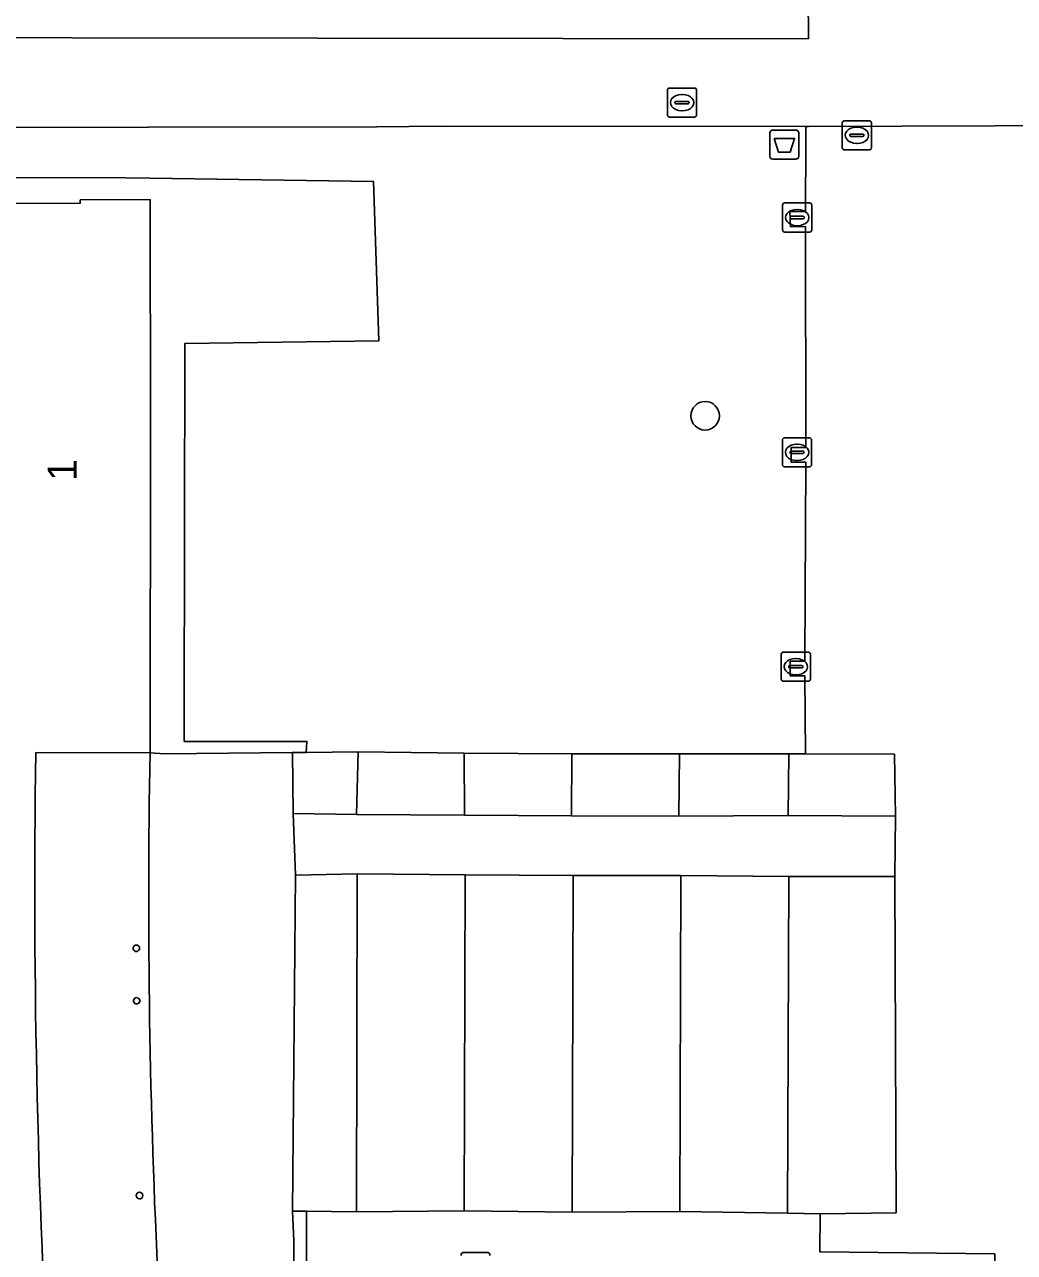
# Model space of a CAD drawing. Extents: x 161477 to 163040, y 383680 to 384871.
# Drawn here: x 162161.99 to 162195.95, y 384149.25 to 384191.39 of the extents above; entities that cross this region are included whole.
import ezdxf

# ---------------------------------------------------------------- set-up
doc = ezdxf.new("R2010")
doc.units = 0
for name, color, linetype in [('IMGEO_Afvalbak', 7, 'Continuous'), ('IMGEO_Boom', 7, 'Continuous'), ('IMGEO_Brandkraan', 7, 'Continuous'), ('IMGEO_Groenvoorziening', 7, 'Continuous'), ('IMGEO_Kolk', 7, 'Continuous'), ('IMGEO_Lichtmast', 7, 'Continuous'), ('IMGEO_Muur', 7, 'Continuous'), ('IMGEO_Pand', 7, 'Continuous'), ('IMGEO_Pand_nummerreeks', 7, 'Continuous'), ('IMGEO_Rioolput', 7, 'Continuous'), ('IMGEO_Voetpad_op_trap', 7, 'Continuous'), ('IMGEO_Voetpad_open', 7, 'Continuous')]:
    doc.layers.add(name, color=color, linetype=linetype)

msp = doc.modelspace()

# ---------------------------------------------------------------- linework, layer by layer
at = {"layer": 'IMGEO_Afvalbak'}
for p, q in [((162187.558, 384186.867), (162187.558, 384187.667)), ((162187.558, 384187.667), (162187.558, 384186.867)), ((162187.658, 384187.767), (162188.448, 384187.767)), ((162188.448, 384187.767), (162187.658, 384187.767)), ((162188.548, 384187.667), (162188.548, 384186.867)), ((162188.548, 384186.867), (162188.548, 384187.667)), ((162188.448, 384186.767), (162187.658, 384186.767)), ((162187.658, 384186.767), (162188.448, 384186.767))]:
    msp.add_line(p, q, dxfattribs=at)
msp.add_lwpolyline([(162187.701, 384187.481), (162188.405, 384187.481), (162188.256, 384187.011), (162187.85, 384187.011), (162187.701, 384187.481)], dxfattribs=at)
for centre, start, end in [((162187.658, 384187.667), 90, 180), ((162187.658, 384187.667), 90, 180), ((162188.448, 384187.667), 0, 90), ((162188.448, 384187.667), 360, 90), ((162187.658, 384186.867), 180, 270), ((162187.658, 384186.867), 180, 270), ((162188.448, 384186.867), 270, 0), ((162188.448, 384186.867), 270, 0)]:
    msp.add_arc(centre, 0.1, start, end, dxfattribs=at)
at = {"layer": 'IMGEO_Boom'}
msp.add_circle((162185.339, 384177.962), 0.489, dxfattribs=at)
at = {"layer": 'IMGEO_Brandkraan'}
for p, q in [((162190.044, 384187.161), (162190.044, 384188.013)), ((162190.119, 384188.087), (162190.971, 384188.087)), ((162191.045, 384188.013), (162191.045, 384187.161)), ((162190.303, 384187.581), (162190.303, 384187.593)), ((162190.741, 384187.544), (162190.343, 384187.544)), ((162190.346, 384187.63), (162190.744, 384187.63)), ((162190.532, 384187.867), (162190.557, 384187.867)), ((162190.787, 384187.593), (162190.787, 384187.581)), ((162190.555, 384187.307), (162190.53, 384187.307)), ((162190.971, 384187.087), (162190.119, 384187.087))]:
    msp.add_line(p, q, dxfattribs=at)
for points in [[(162190.044, 384187.161), (162190.044, 384188.013)], [(162190.119, 384188.087), (162190.971, 384188.087)], [(162191.045, 384188.013), (162191.045, 384187.161)], [(162190.971, 384187.087), (162190.119, 384187.087)]]:
    msp.add_lwpolyline(points, dxfattribs=at)
for centre, radius, start, end in [((162190.121, 384188.011), 0.0765, 91.552, 178.448), ((162190.121, 384188.011), 0.0765, 91.552, 178.448), ((162190.969, 384188.011), 0.0765, 1.552, 88.448), ((162190.969, 384188.011), 0.0765, 1.552, 88.448), ((162190.343, 384187.59), 0.0403, 85.8775, 175.7526), ((162190.34, 384187.58), 0.0366, 178.938, 274.7102), ((162190.744, 384187.587), 0.043, 264.8664, 352.4533), ((162190.748, 384187.592), 0.0386, 1.7309, 96.639), ((162190.121, 384187.163), 0.0765, 181.552, 268.448), ((162190.121, 384187.163), 0.0765, 181.552, 268.448), ((162190.969, 384187.163), 0.0765, 271.552, 358.448), ((162190.969, 384187.163), 0.0765, 271.552, 358.448)]:
    msp.add_arc(centre, radius, start, end, dxfattribs=at)
for centre, major_axis, ratio, start_param, end_param in [((162190.531, 384187.587), (-0.387, 0.002), 0.722429, 4.712389, 7.853982), ((162190.556, 384187.587), (-0.39, 0.002), 0.717154, 1.570796, 4.712389)]:
    msp.add_ellipse(centre, major_axis=major_axis, ratio=ratio, start_param=start_param, end_param=end_param, dxfattribs=at)
at = {"layer": 'IMGEO_Groenvoorziening'}
for points in [[(162104.681, 384192.792), (162104.654, 384191.016), (162188.881, 384190.9), (162188.873, 384192.38)], [(162155.137, 384186.146), (162165.447, 384186.122), (162166.287, 384186.12), (162173.964, 384185.999), (162174.149, 384180.537), (162167.49, 384180.44), (162167.473, 384167.492), (162167.472, 384166.788), (162171.68, 384166.786), (162171.652, 384166.414), (162173.434, 384166.426), (162177.077, 384166.387), (162180.765, 384166.363), (162184.462, 384166.363), (162188.21, 384166.358), (162188.781, 384166.357), (162188.757, 384169.041), (162188.257, 384169.043), (162188.259, 384169.543), (162188.759, 384169.541), (162188.787, 384176.376), (162188.287, 384176.375), (162188.287, 384176.875), (162188.787, 384176.876), (162188.78, 384184.461), (162188.267, 384184.45), (162188.245, 384184.974), (162188.776, 384184.968), (162188.79, 384187.341), (162188.794, 384187.886), (162176.282, 384187.902), (162174.081, 384187.881), (162166.246, 384187.869), (162148.931, 384187.832)]]:
    msp.add_lwpolyline(points, dxfattribs=at)
for points in [[(162173.964, 384185.999), (162166.287, 384186.12), (162165.447, 384186.122), (162155.137, 384186.146), (162149.501, 384186.002), (162149.508, 384185.702), (162149.52, 384185.242), (162163.904, 384185.258), (162163.904, 384185.368), (162166.305, 384185.379), (162166.305, 384185.279), (162166.316, 384177.667), (162166.297, 384166.401), (162166.795, 384166.359), (162171.183, 384166.409), (162171.652, 384166.414), (162171.68, 384166.786), (162167.472, 384166.788), (162167.473, 384167.492), (162167.49, 384180.44), (162174.149, 384180.537)], [(162195.277, 384149.207), (162189.268, 384149.278), (162189.285, 384150.584), (162188.164, 384150.602), (162184.472, 384150.653), (162180.775, 384150.64), (162177.072, 384150.682), (162173.379, 384150.65), (162171.665, 384150.667), (162171.665, 384149.89), (162171.667, 384147.235), (162172.666, 384147.297), (162173.098, 384141.826), (162173.243, 384140.073), (162195.003, 384142.981), (162195.257, 384143.015), (162195.259, 384143.722)]]:
    msp.add_lwpolyline(points, close=True, dxfattribs=at)
at = {"layer": 'IMGEO_Kolk'}
for p, q in [((162187.996, 384184.338), (162187.996, 384185.19)), ((162188.071, 384185.264), (162188.923, 384185.264)), ((162188.484, 384185.044), (162188.509, 384185.044)), ((162188.997, 384185.19), (162188.997, 384184.338)), ((162188.255, 384184.758), (162188.255, 384184.77)), ((162188.693, 384184.721), (162188.295, 384184.721)), ((162188.298, 384184.807), (162188.696, 384184.807)), ((162188.739, 384184.77), (162188.739, 384184.758)), ((162188.923, 384184.264), (162188.071, 384184.264)), ((162188.507, 384184.484), (162188.482, 384184.484)), ((162187.99, 384176.282), (162187.99, 384177.134)), ((162188.065, 384177.208), (162188.917, 384177.208)), ((162188.478, 384176.988), (162188.503, 384176.988)), ((162188.991, 384177.134), (162188.991, 384176.282)), ((162188.249, 384176.702), (162188.249, 384176.714)), ((162188.687, 384176.665), (162188.289, 384176.665)), ((162188.292, 384176.751), (162188.69, 384176.751)), ((162188.733, 384176.714), (162188.733, 384176.702)), ((162188.917, 384176.208), (162188.065, 384176.208)), ((162188.501, 384176.428), (162188.476, 384176.428)), ((162188.026, 384169.852), (162188.878, 384169.852)), ((162187.951, 384168.926), (162187.951, 384169.778)), ((162188.439, 384169.632), (162188.464, 384169.632)), ((162188.952, 384169.778), (162188.952, 384168.926)), ((162188.21, 384169.346), (162188.21, 384169.358)), ((162188.648, 384169.309), (162188.25, 384169.309)), ((162188.253, 384169.395), (162188.651, 384169.395)), ((162188.462, 384169.072), (162188.437, 384169.072)), ((162188.694, 384169.358), (162188.694, 384169.346)), ((162188.878, 384168.852), (162188.026, 384168.852))]:
    msp.add_line(p, q, dxfattribs=at)
for points in [[(162187.996, 384184.338), (162187.996, 384185.19)], [(162188.071, 384185.264), (162188.923, 384185.264)], [(162188.997, 384185.19), (162188.997, 384184.338)], [(162188.923, 384184.264), (162188.071, 384184.264)], [(162187.99, 384176.282), (162187.99, 384177.134)], [(162188.065, 384177.208), (162188.917, 384177.208)], [(162188.991, 384177.134), (162188.991, 384176.282)], [(162188.917, 384176.208), (162188.065, 384176.208)], [(162188.026, 384169.852), (162188.878, 384169.852)], [(162187.951, 384168.926), (162187.951, 384169.778)], [(162188.952, 384169.778), (162188.952, 384168.926)], [(162188.878, 384168.852), (162188.026, 384168.852)]]:
    msp.add_lwpolyline(points, dxfattribs=at)
for centre, radius, start, end in [((162188.073, 384185.188), 0.0765, 91.552, 178.448), ((162188.073, 384185.188), 0.0765, 91.552, 178.448), ((162188.921, 384185.188), 0.0765, 1.552, 88.448), ((162188.921, 384185.188), 0.0765, 1.552, 88.448), ((162188.295, 384184.767), 0.0403, 85.8775, 175.7526), ((162188.292, 384184.757), 0.0366, 178.938, 274.7102), ((162188.696, 384184.764), 0.043, 264.8664, 352.4533), ((162188.7, 384184.769), 0.0386, 1.7309, 96.639), ((162188.073, 384184.34), 0.0765, 181.552, 268.448), ((162188.073, 384184.34), 0.0765, 181.552, 268.448), ((162188.921, 384184.34), 0.0765, 271.552, 358.448), ((162188.921, 384184.34), 0.0765, 271.552, 358.448), ((162188.067, 384177.132), 0.0765, 91.552, 178.448), ((162188.067, 384177.132), 0.0765, 91.552, 178.448), ((162188.915, 384177.132), 0.0765, 1.552, 88.448), ((162188.915, 384177.132), 0.0765, 1.552, 88.448), ((162188.289, 384176.711), 0.0403, 85.8775, 175.7526), ((162188.286, 384176.701), 0.0366, 178.938, 274.7102), ((162188.69, 384176.708), 0.043, 264.8664, 352.4533), ((162188.694, 384176.713), 0.0386, 1.7309, 96.639), ((162188.067, 384176.284), 0.0765, 181.552, 268.448), ((162188.067, 384176.284), 0.0765, 181.552, 268.448), ((162188.915, 384176.284), 0.0765, 271.552, 358.448), ((162188.915, 384176.284), 0.0765, 271.552, 358.448), ((162188.028, 384169.776), 0.0765, 91.552, 178.448), ((162188.028, 384169.776), 0.0765, 91.552, 178.448), ((162188.876, 384169.776), 0.0765, 1.552, 88.448), ((162188.876, 384169.776), 0.0765, 1.552, 88.448), ((162188.25, 384169.355), 0.0403, 85.8775, 175.7526), ((162188.247, 384169.345), 0.0366, 178.938, 274.7102), ((162188.651, 384169.352), 0.043, 264.8664, 352.4533), ((162188.655, 384169.357), 0.0386, 1.7309, 96.639), ((162188.028, 384168.928), 0.0765, 181.552, 268.448), ((162188.028, 384168.928), 0.0765, 181.552, 268.448), ((162188.876, 384168.928), 0.0765, 271.552, 358.448), ((162188.876, 384168.928), 0.0765, 271.552, 358.448)]:
    msp.add_arc(centre, radius, start, end, dxfattribs=at)
for centre, major_axis, ratio, start_param, end_param in [((162188.483, 384184.764), (-0.387, 0.002), 0.722429, 4.712389, 7.853982), ((162188.508, 384184.764), (-0.39, 0.002), 0.717154, 1.570796, 4.712389), ((162188.477, 384176.708), (-0.387, 0.002), 0.722429, 4.712389, 7.853982), ((162188.502, 384176.708), (-0.39, 0.002), 0.717154, 1.570796, 4.712389), ((162188.438, 384169.352), (-0.387, 0.002), 0.722429, 4.712389, 7.853982), ((162188.463, 384169.352), (-0.39, 0.002), 0.717154, 1.570796, 4.712389)]:
    msp.add_ellipse(centre, major_axis=major_axis, ratio=ratio, start_param=start_param, end_param=end_param, dxfattribs=at)
at = {"layer": 'IMGEO_Lichtmast'}
for p, q in [((162177.067, 384149.254), (162177.857, 384149.254)), ((162177.857, 384149.254), (162177.067, 384149.254))]:
    msp.add_line(p, q, dxfattribs=at)
for centre, start, end in [((162177.067, 384149.154), 90, 180), ((162177.067, 384149.154), 90, 180), ((162177.857, 384149.154), 0, 90), ((162177.857, 384149.154), 360, 90)]:
    msp.add_arc(centre, 0.1, start, end, dxfattribs=at)
at = {"layer": 'IMGEO_Muur'}
msp.add_lwpolyline([(162171.667, 384147.235), (162171.665, 384149.89), (162171.665, 384150.667), (162171.189, 384150.672), (162171.234, 384149.651), (162171.223, 384147.253)], dxfattribs=at)
at = {"layer": 'IMGEO_Pand'}
msp.add_lwpolyline([(162162.377, 384166.407), (162166.297, 384166.401), (162166.316, 384177.667), (162166.305, 384185.279), (162166.305, 384185.379), (162163.904, 384185.368), (162163.904, 384185.258), (162149.52, 384185.242), (162147.865, 384185.24), (162061.36, 384185.144)], dxfattribs=at)
for centre, radius, start, end in [((162474.563, 384161.839), 312.22, 179.16169, 183.5032), ((162165.827, 384159.691), 0.111, 33.528, 253.2831), ((162165.828, 384159.69), 0.11, 252.7297, 34.0814), ((162165.838, 384157.889), 0.109, 33.548, 302.6747), ((162165.839, 384157.889), 0.108, 302.3757, 33.847), ((162165.939, 384151.206), 0.113, 49.5701, 310.4299), ((162165.94, 384151.206), 0.112, 310.1122, 49.8878)]:
    msp.add_arc(centre, radius, start, end, dxfattribs=at)
at = {"layer": 'IMGEO_Rioolput'}
for p, q in [((162184.12, 384189.209), (162184.972, 384189.209)), ((162184.045, 384188.283), (162184.045, 384189.135)), ((162184.533, 384188.989), (162184.558, 384188.989)), ((162185.046, 384189.135), (162185.046, 384188.283)), ((162184.304, 384188.703), (162184.304, 384188.715)), ((162184.742, 384188.666), (162184.344, 384188.666)), ((162184.347, 384188.752), (162184.745, 384188.752)), ((162184.556, 384188.429), (162184.531, 384188.429)), ((162184.788, 384188.715), (162184.788, 384188.703)), ((162184.972, 384188.209), (162184.12, 384188.209))]:
    msp.add_line(p, q, dxfattribs=at)
for points in [[(162184.12, 384189.209), (162184.972, 384189.209)], [(162184.045, 384188.283), (162184.045, 384189.135)], [(162185.046, 384189.135), (162185.046, 384188.283)], [(162184.972, 384188.209), (162184.12, 384188.209)]]:
    msp.add_lwpolyline(points, dxfattribs=at)
for centre, radius, start, end in [((162184.122, 384189.133), 0.0765, 91.552, 178.448), ((162184.122, 384189.133), 0.0765, 91.552, 178.448), ((162184.97, 384189.133), 0.0765, 1.552, 88.448), ((162184.97, 384189.133), 0.0765, 1.552, 88.448), ((162184.344, 384188.712), 0.0403, 85.8775, 175.7526), ((162184.341, 384188.702), 0.0366, 178.938, 274.7102), ((162184.745, 384188.709), 0.043, 264.8664, 352.4533), ((162184.749, 384188.714), 0.0386, 1.7309, 96.639), ((162184.122, 384188.285), 0.0765, 181.552, 268.448), ((162184.122, 384188.285), 0.0765, 181.552, 268.448), ((162184.97, 384188.285), 0.0765, 271.552, 358.448), ((162184.97, 384188.285), 0.0765, 271.552, 358.448)]:
    msp.add_arc(centre, radius, start, end, dxfattribs=at)
for centre, major_axis, ratio, start_param, end_param in [((162184.532, 384188.709), (-0.387, 0.002), 0.722429, 4.712389, 7.853982), ((162184.557, 384188.709), (-0.39, 0.002), 0.717154, 1.570796, 4.712389)]:
    msp.add_ellipse(centre, major_axis=major_axis, ratio=ratio, start_param=start_param, end_param=end_param, dxfattribs=at)
at = {"layer": 'IMGEO_Voetpad_op_trap'}
for points in [[(162173.434, 384166.426), (162171.652, 384166.414), (162171.183, 384166.409), (162171.207, 384164.316), (162173.382, 384164.281)], [(162177.077, 384166.387), (162173.434, 384166.426), (162173.382, 384164.281), (162177.087, 384164.255)], [(162180.765, 384166.363), (162177.077, 384166.387), (162177.087, 384164.255), (162180.757, 384164.236)], [(162184.462, 384166.363), (162180.765, 384166.363), (162180.757, 384164.236), (162184.438, 384164.225)], [(162188.21, 384166.358), (162184.462, 384166.363), (162184.438, 384164.225), (162188.189, 384164.251)], [(162191.837, 384166.35), (162188.781, 384166.357), (162188.21, 384166.358), (162188.189, 384164.251), (162191.873, 384164.221)], [(162173.407, 384162.25), (162171.289, 384162.195), (162171.189, 384150.672), (162171.665, 384150.667), (162173.379, 384150.65)], [(162177.112, 384162.209), (162173.407, 384162.25), (162173.379, 384150.65), (162177.072, 384150.682)], [(162180.81, 384162.192), (162177.112, 384162.209), (162177.072, 384150.682), (162180.775, 384150.64)], [(162184.506, 384162.192), (162180.81, 384162.192), (162180.775, 384150.64), (162184.472, 384150.653)], [(162188.205, 384162.158), (162184.506, 384162.192), (162184.472, 384150.653), (162188.164, 384150.602)], [(162191.85, 384162.152), (162188.205, 384162.158), (162188.164, 384150.602), (162189.285, 384150.584), (162191.888, 384150.614)]]:
    msp.add_lwpolyline(points, close=True, dxfattribs=at)
at = {"layer": 'IMGEO_Voetpad_open'}
for points in [[(162188.873, 384192.38), (162188.881, 384190.9), (162104.654, 384191.016), (162102.274, 384191.019), (162083.053, 384190.907), (162080.169, 384190.88), (162056.233, 384190.888), (162041.924, 384190.961), (162036.69, 384190.945), (162021.037, 384190.964), (161965.965, 384191.055), (161965.985, 384199.331)], [(162111.682, 384187.774), (162130.783, 384187.804), (162148.931, 384187.832), (162166.246, 384187.869), (162174.081, 384187.881), (162176.282, 384187.902), (162188.794, 384187.886), (162188.88, 384187.886), (162198.463, 384187.921), (162202.167, 384187.934), (162219.54, 384187.974), (162232.681, 384187.987)], [(162198.463, 384187.921), (162188.88, 384187.886), (162188.794, 384187.886), (162188.79, 384187.341), (162188.776, 384184.968), (162188.245, 384184.974), (162188.267, 384184.45), (162188.78, 384184.461), (162188.787, 384176.876), (162188.287, 384176.875), (162188.287, 384176.375), (162188.787, 384176.376), (162188.759, 384169.541), (162188.259, 384169.543), (162188.257, 384169.043), (162188.757, 384169.041), (162188.781, 384166.357), (162191.837, 384166.35), (162191.873, 384164.221), (162191.85, 384162.152), (162191.888, 384150.614), (162189.285, 384150.584), (162189.268, 384149.278), (162195.277, 384149.207)], [(162166.297, 384166.401), (162162.377, 384166.407)], [(162171.289, 384162.195), (162171.207, 384164.316), (162171.183, 384166.409), (162166.795, 384166.359), (162166.297, 384166.401)], [(162168.116, 384129.857), (162173.837, 384130.569), (162173.133, 384136.8), (162172.691, 384141.661), (162172.279, 384146.85), (162171.221, 384146.773), (162171.223, 384147.253), (162171.234, 384149.651), (162171.189, 384150.672), (162171.289, 384162.195)]]:
    msp.add_lwpolyline(points, dxfattribs=at)
msp.add_lwpolyline([(162191.873, 384164.221), (162188.189, 384164.251), (162184.438, 384164.225), (162180.757, 384164.236), (162177.087, 384164.255), (162173.382, 384164.281), (162171.207, 384164.316), (162171.289, 384162.195), (162173.407, 384162.25), (162177.112, 384162.209), (162180.81, 384162.192), (162184.506, 384162.192), (162188.205, 384162.158), (162191.85, 384162.152)], close=True, dxfattribs=at)
for centre, radius, start, end in [((162474.563, 384161.839), 312.22, 179.16169, 183.5032), ((162434.203, 384161.419), 267.952, 178.93462, 186.76454), ((162434.203, 384161.419), 267.952, 178.93462, 186.76454), ((162165.827, 384159.691), 0.111, 33.528, 253.2831), ((162165.828, 384159.69), 0.11, 252.7297, 34.0814), ((162165.838, 384157.889), 0.109, 33.548, 302.6747), ((162165.839, 384157.889), 0.108, 302.3757, 33.847), ((162165.939, 384151.206), 0.113, 49.5701, 310.4299), ((162165.94, 384151.206), 0.112, 310.1122, 49.8878)]:
    msp.add_arc(centre, radius, start, end, dxfattribs=at)

# ---------------------------------------------------------------- texts
at = {"layer": 'IMGEO_Pand_nummerreeks'}
msp.add_text('1', height=1, rotation=89.9773, dxfattribs=at).set_placement((162163.781, 384175.729))

doc.saveas('drawing.dxf')
